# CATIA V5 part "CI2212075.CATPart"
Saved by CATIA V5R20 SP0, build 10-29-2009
Part number: CI2212075
Bounding box of the stored display mesh (mm): x -12 to 12, y -9.46 to 93, z -16.675 to 13.021
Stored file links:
  C:\Users\Raffaele\Desktop\3D X SITO CF\BOLEX\19-INCLINED ASSEMBLY REF_CI\CI2212075.CATPart
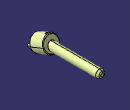
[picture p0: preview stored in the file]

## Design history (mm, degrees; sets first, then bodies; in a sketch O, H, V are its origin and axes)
Set1
  DatumSurface1 to DatumSurface16 "MANIFOLD_SOLID_BREP #379"
  DatumSurface17 to DatumSurface39 "MANIFOLD_SOLID_BREP #1129"
Body1 (main body)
